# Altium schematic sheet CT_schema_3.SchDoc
size 527 x 503 mm
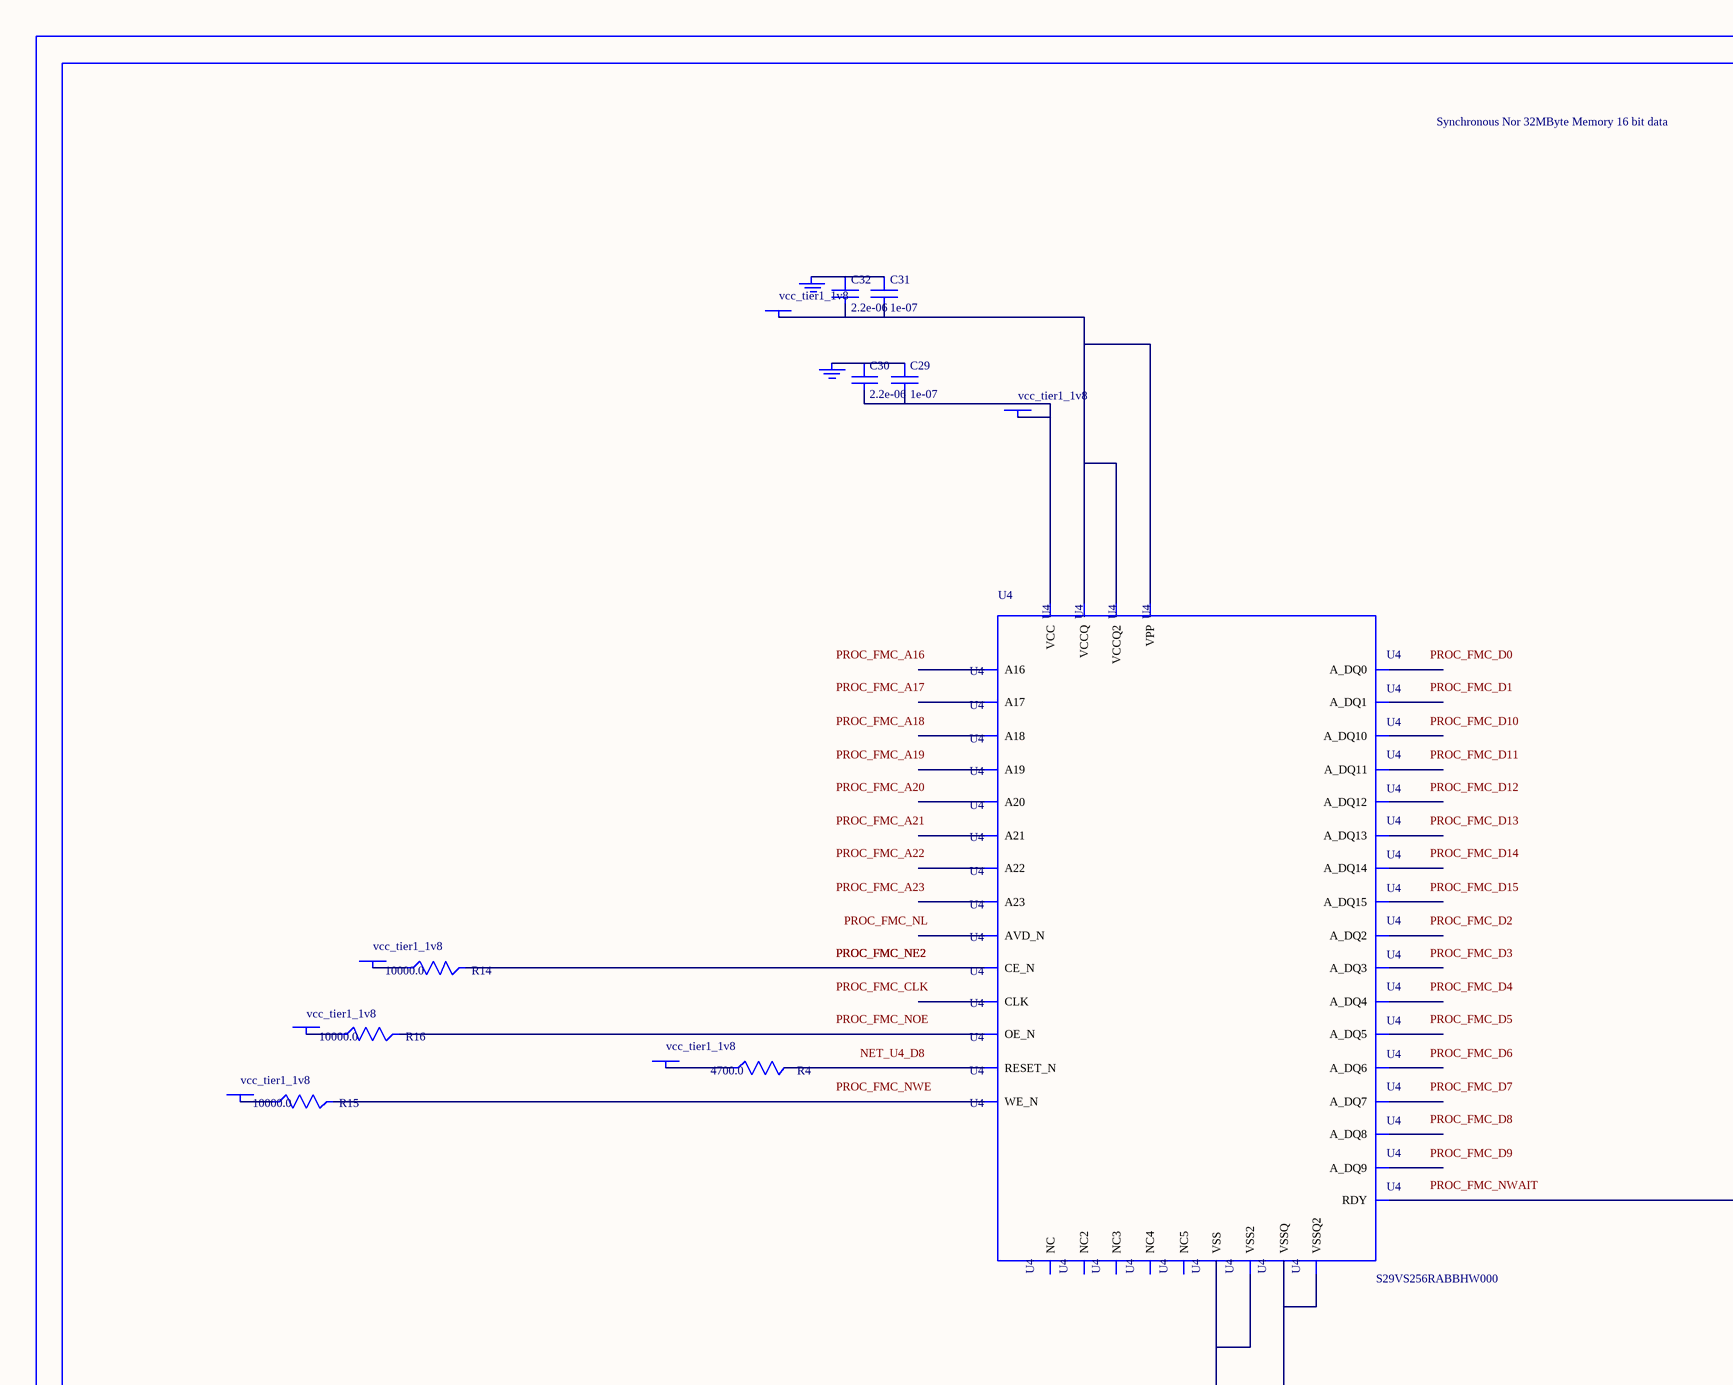
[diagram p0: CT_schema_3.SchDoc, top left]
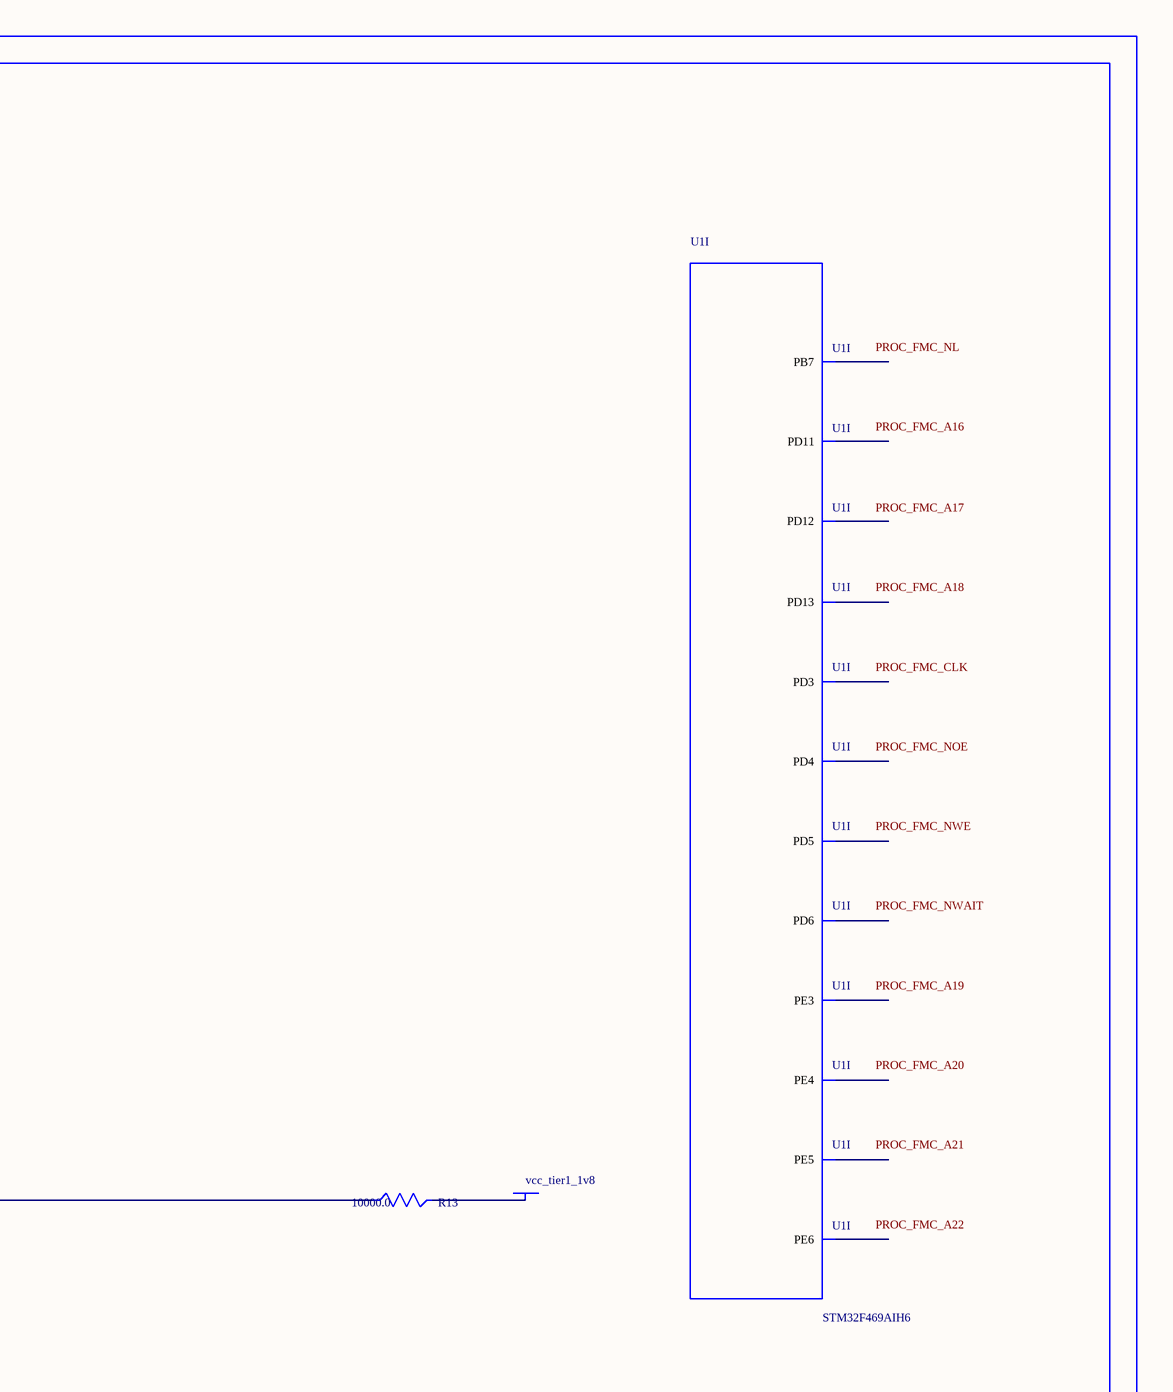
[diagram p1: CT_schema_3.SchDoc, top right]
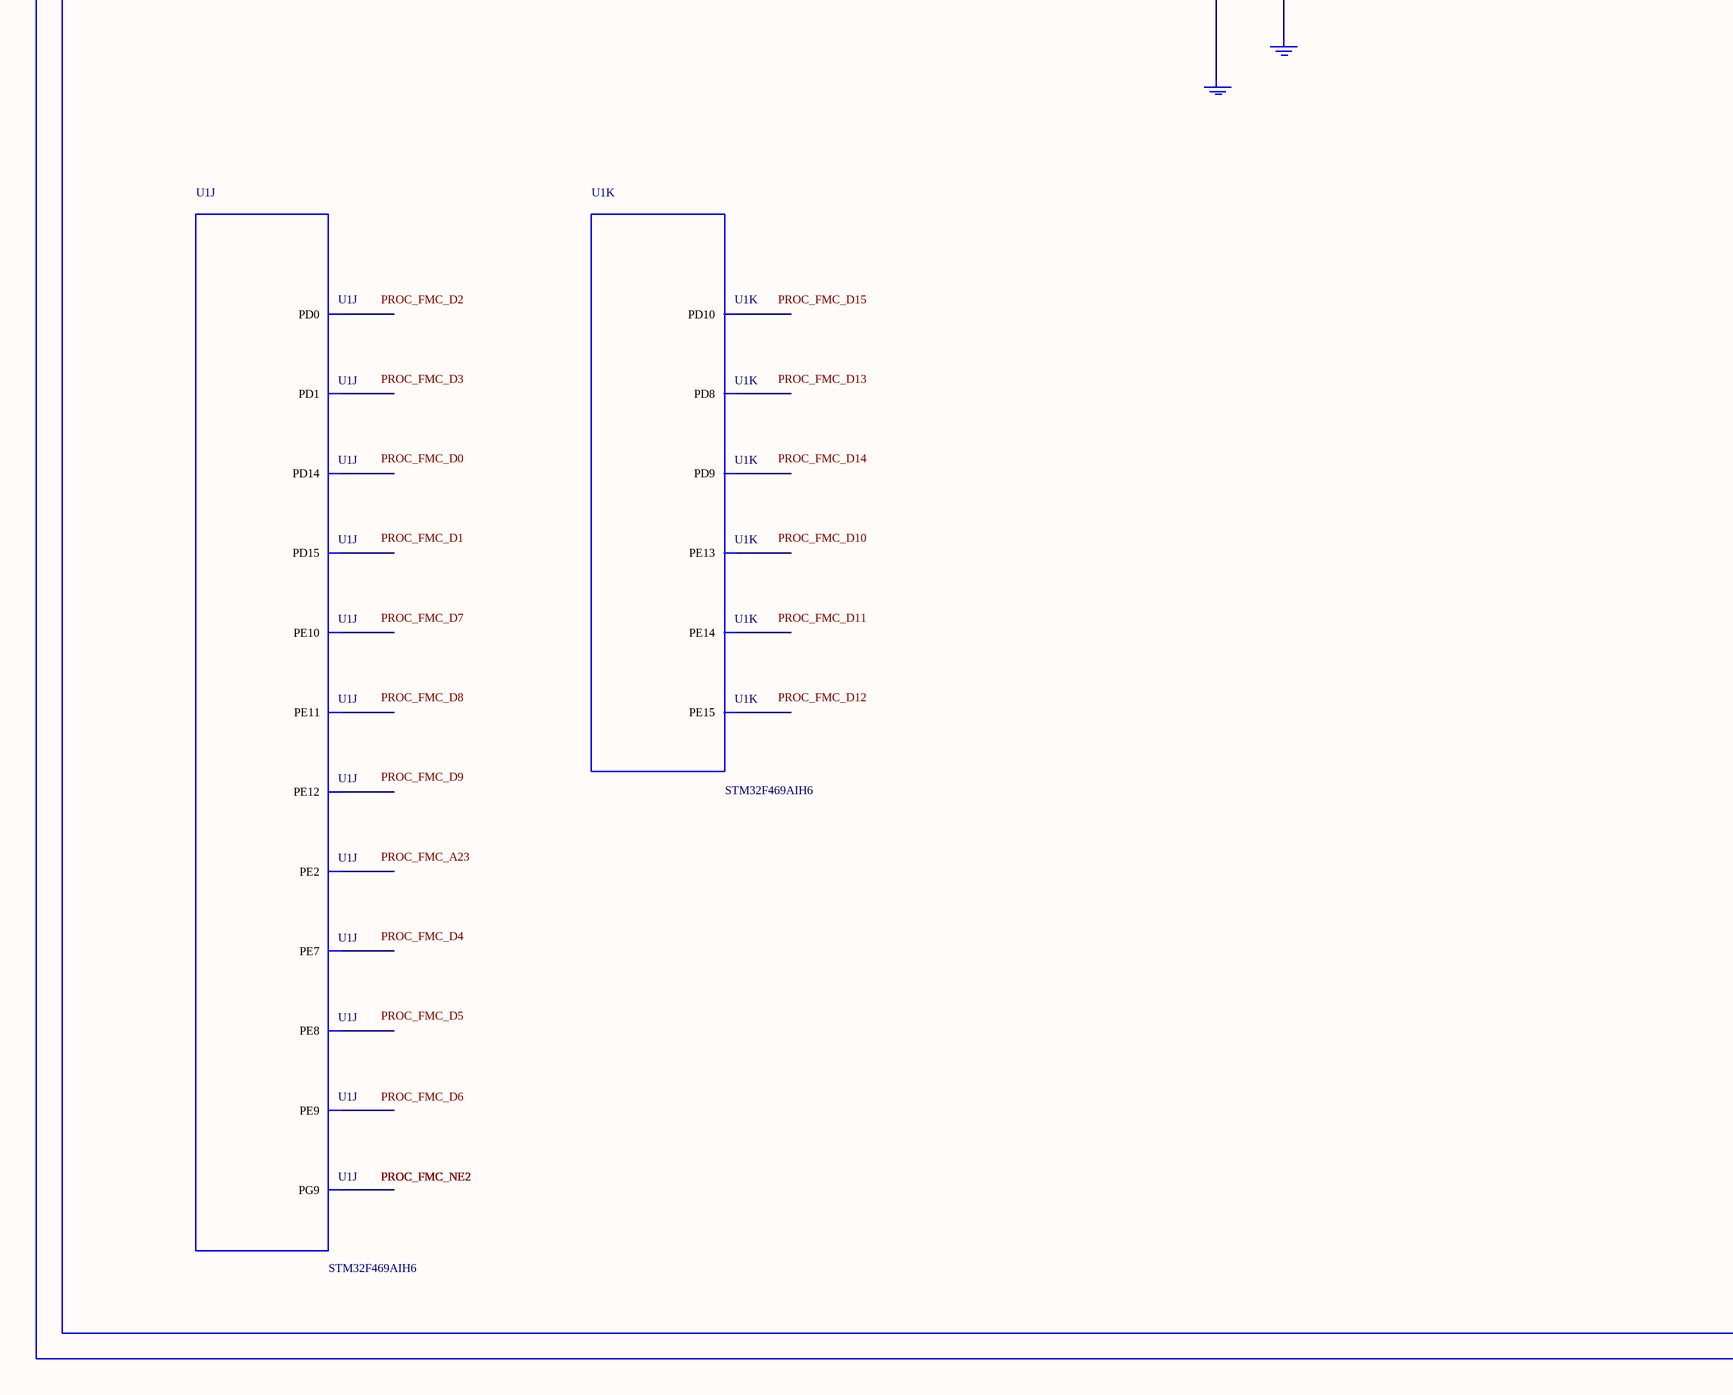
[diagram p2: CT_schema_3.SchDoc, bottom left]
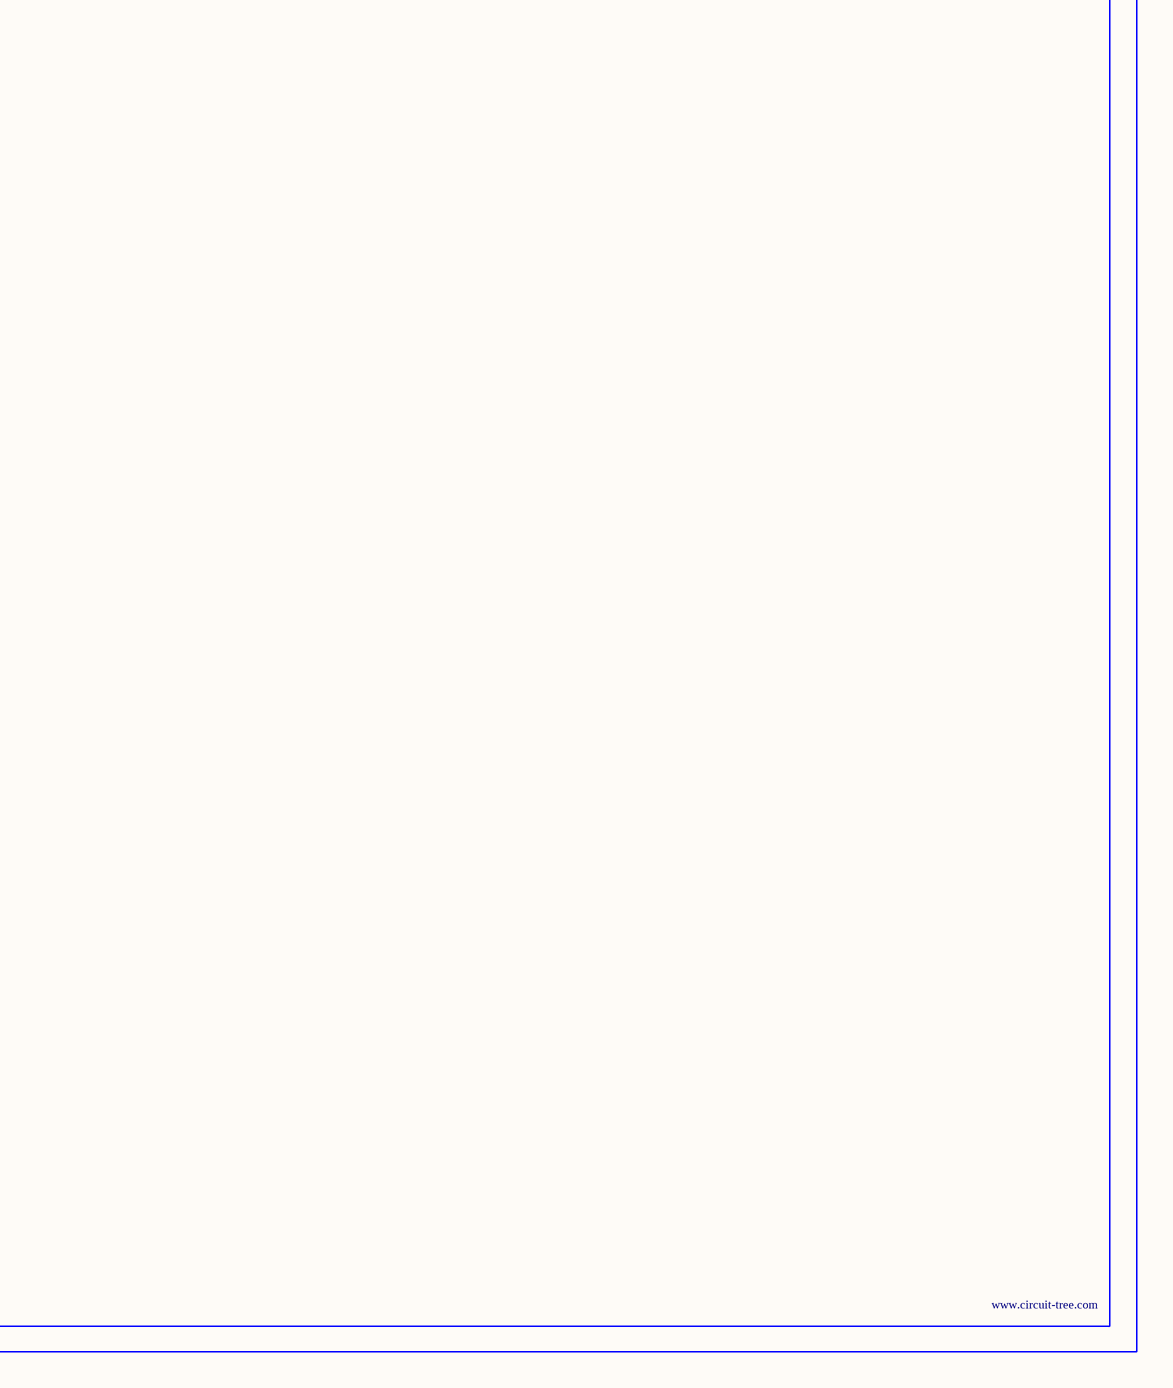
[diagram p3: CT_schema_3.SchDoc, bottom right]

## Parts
BORDER2  (no value)
C29  1e-07  [C0402]
C30  2.2e-06  [C0603]
C31  1e-07  [C0402]
C32  2.2e-06  [C0603]
GND_INSTANCE_2_0  (no value)
GND_INSTANCE_2_1  (no value)
GND_INSTANCE_2_2  (no value)
GND_INSTANCE_2_3  (no value)
POWER_INSTANCE_2_0  vcc_tier1_1v8
POWER_INSTANCE_2_1  vcc_tier1_1v8
POWER_INSTANCE_2_2  vcc_tier1_1v8
POWER_INSTANCE_2_3  vcc_tier1_1v8
POWER_INSTANCE_2_4  vcc_tier1_1v8
POWER_INSTANCE_2_5  vcc_tier1_1v8
POWER_INSTANCE_2_6  vcc_tier1_1v8
R4  4700.0  [R0603]
R13  10000.0  [R0603]
R14  10000.0  [R0603]
R15  10000.0  [R0603]
R16  10000.0  [R0603]
U1  STM32F469AIH6  [UFBGA169]  (parts I,J,K of 13)
U4  S29VS256RABBHW000  [S29VS256RABBHW000]

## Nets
NetC29_1: C29.1 C30.1 GND_INSTANCE_2_0.0(GND)
NetC29_2: C29.2 C30.2 POWER_INSTANCE_2_0.0(PWR) U4.C7(VCC)
NetC31_1: C31.1 C32.1 GND_INSTANCE_2_1.0(GND)
NetC31_2: C31.2 C32.2 POWER_INSTANCE_2_1.0(PWR) U4.C9(VPP) U4.D3(VCCQ) U4.F10(VCCQ2)
NetGND_INSTANCE_2_2_0: GND_INSTANCE_2_2.0(GND) U4.C5(VSS) U4.D12(VSS2)
NetGND_INSTANCE_2_3_0: GND_INSTANCE_2_3.0(GND) U4.E3(VSSQ) U4.F5(VSSQ2)
NetPOWER_INSTANCE_2_2_0: POWER_INSTANCE_2_2.0(PWR) R13.2
NetPOWER_INSTANCE_2_3_0: POWER_INSTANCE_2_3.0(PWR) R14.1
NetPOWER_INSTANCE_2_4_0: POWER_INSTANCE_2_4.0(PWR) R15.1
NetPOWER_INSTANCE_2_5_0: POWER_INSTANCE_2_5.0(PWR) R16.1
NetPOWER_INSTANCE_2_6_0: POWER_INSTANCE_2_6.0(PWR) R4.1
NetR4_2: R4.2 U4.D8(RESET_N)
NetR13_1: R13.1 U4.C3(RDY)
NetR14_2: R14.2 U4.D11(CE_N)
NetR15_2: R15.2 U4.C8(WE_N)
NetR16_2: R16.2 U4.E12(OE_N)

Not connected (* = marked no-connect by the designer): U1 B2(PE2) B4(PB7) B7(PD5) C1(PE3) C2(PE4) C6(PD4) C7(PD1) C8(PD3) C9(PD0) D1(PE5) D2(PE6) D7(PD6) E6(PG9) G6(PE8) H6(PE9) H7(PE10) J8(PE13) K7(PE11) K8(PE14) L7(PE12) L8(PE15) L10(PD8) L11(PD10) L12(PD14) L13(PD15) M10(PD9) M11(PD11) M12(PD13) M13(PD12) N7(PE7); U4 A1(NC) A14(NC2) C4(A21) C6(CLK) C10(A19) C11(A17) C12(A22) D4(A16) D5(A20) D6(AVD_N) D7(A23) D9(NC3) D10(A18) E4(A_DQ8) E5(A_DQ9) E6(A_DQ2) E7(A_DQ3) E8(A_DQ12) E9(A_DQ13) E10(A_DQ6) E11(A_DQ7) F3(A_DQ0) F4(A_DQ1) F6(A_DQ10) F7(A_DQ11) F8(A_DQ4) F9(A_DQ5) F11(A_DQ14) F12(A_DQ15) H1(NC4) H14(NC5)

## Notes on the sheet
- Labels drawn without touching a wire or pin: NET_U4_D8, PROC_FMC_A16, PROC_FMC_A17, PROC_FMC_A18, PROC_FMC_A19, PROC_FMC_A20, PROC_FMC_A21, PROC_FMC_A22, PROC_FMC_A23, PROC_FMC_CLK, PROC_FMC_D0, PROC_FMC_D1, PROC_FMC_D2, PROC_FMC_D3, PROC_FMC_D4, PROC_FMC_D5, PROC_FMC_D6, PROC_FMC_D7, PROC_FMC_D8, PROC_FMC_D9, PROC_FMC_D10, PROC_FMC_D11, PROC_FMC_D12, PROC_FMC_D13, PROC_FMC_D14, PROC_FMC_D15, PROC_FMC_NL, PROC_FMC_NOE, PROC_FMC_NWAIT, PROC_FMC_NWE

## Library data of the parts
BORDER2 = BORDER_PAGE2
C29 C31 = C0402C104K3RACTU
C30 C32 = C0603C225K8RACTU
GND_INSTANCE_2_0-GND_INSTANCE_2_3 = GND
POWER_INSTANCE_2_0-POWER_INSTANCE_2_6 = PWR
R4 = RC0603JR-074K7L
R13-R16 = RC0603JR-0710KL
